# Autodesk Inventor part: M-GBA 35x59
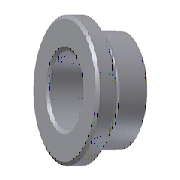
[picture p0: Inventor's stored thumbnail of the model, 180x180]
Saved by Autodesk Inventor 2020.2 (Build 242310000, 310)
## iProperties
Manager: www.cadconsulting.pl
Company: Fabian Stasiak CAD Consulting
Created: 2014-02
Part Number: M-GBA 35x59
Material: SUJ 2
Description: GUIDE BUSH
Document SubType Name: Modeling
Designer: F.Stasiak
Standard Revision: 1
Manufacturer: FUTABA
Language: pl-PL
Size Designation: 35x59
Categories: <MemberInstance><Categories><Category DisplayName="Forma wtryskowa" InternalName="349578f2-f4d4-4954-8c09-8e99297a61c0" Mnemonic="MOLD"><Category DisplayName="K
Density: 7.85 g/cm^3
Appearance: Domyślna
Catalog Web Link: www.expertbooks.pl
IsCustomPart: 0
Author: F.Stasiak
Subject: Zbiór ćwiczeń. Autodesk Inventor 2020. Kurs Professional
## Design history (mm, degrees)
sketch "Sketch1"
  geometry: L1 (0, -16.2)-(0, 6.2) reference; L2 (0, 10)-(27, 10); L3 (27, 10)-(27, 0); L4 (27, 0)-(23.5, 0); L5 (23.5, 0)-(23.5, -2); L6 (23.5, -2)-(24, -2); L7 (24, -2)-(24, -46); L8 (24, -46)-(23.75, -46); L9 (23.75, -46)-(23.75, -49); L10 (23.75, -49)-(0, -49); 1 further point
  constraints: 18 end point, 4 perpendicular, 2 parallel, 2 point on line, 1 horizontal alignment
  dimensions: "d0" = 59 distance between parallel lines of L10 L2 (= B); "d2" = 10 distance between parallel lines of L4 L2 (= T1); "d3" = 48 diameter of L7 L1 (= D); "d4" = 3 distance between parallel lines of L10 L8; "d5" = 47.5 diameter of L9 L1 (= D_Guide); "d6" = 54 diameter of L3 L1 (= D2); "d7" = 0.5 distance between parallel lines of L7 L5; "d8" = 2 distance between parallel lines of L4 L6
revolve "Revolution1" sketch "Sketch1" stored, may be unused: angle "d13" = 90 deg
sketch "Sketch2"
  geometry: L1 (-23.75, -49)-(23.75, -49) reference; L2 (0, -20.2)-(0, 30.2) reference; L3 (17.5, 10)-(17.5, -49); L4 (17.5, 10)-(17.75, 10); L5 (17.75, 10)-(17.75, 69); L6 (17.75, 69)-(0, 69); L7 (17.5, -49)-(0, -49); L8 (0, 69)-(0, -49)
  constraints: 12 end point, 3 perpendicular, 3 point on line, 1 collinear, 1 midpoint, 1 parallel
  dimensions: "d18" = 35 diameter of L3 L2 (= d_); "d20" = 59 distance between parallel lines of L1 L4 (= L1); "d21" = 59 distance between parallel lines of L4 L6 (= B); "d22" = 35.5 diameter of L5 L2 (= d1)
revolve "Revolution2" sketch "Sketch2" stored, may be unused: angle "d23" = 90 deg
chamfer "Chamfer1" distance "d24" = 0.5; stored, may be unused: second distance "d25" = 2, angle "d26" = 45 deg
fillet "Fillet1" dims "d27" = 0.3
fillet "Fillet2" dims "d28" = 0.8
body "Solid1"
other parameters: "d_" = 35 [user parameter; used in 1 equation term], "d1" = 35.5 [user parameter; used in 1 equation term], "L1" = 59 [user parameter; used in 1 equation term], "D" = 48 [user parameter; used in 1 equation term], "D2" = 54 [user parameter; used in 1 equation term], "B" = 59 [user parameter; used in 2 equation terms], "T1" = 10 [user parameter; used in 1 equation term], "D_Guide" = 47.5 [user parameter; used in 1 equation term], "d29" = 0, "d30" = 0, "d31" = 0
